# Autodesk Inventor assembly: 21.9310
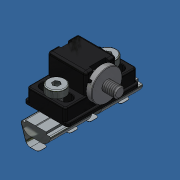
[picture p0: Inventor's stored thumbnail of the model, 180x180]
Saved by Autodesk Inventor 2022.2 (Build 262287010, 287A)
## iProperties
Created: 2022-08
Part Number: 21.9310
Document SubType Name: Assembly
Designer: amoles
Description: MAGNETIC CATCH 30
Stock Number: 21.9310 MAGNETIC CATCH 30
Author: amoles
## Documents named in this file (5)
- L:\INVENTOR LIBRARIES\PARTS LIBRARY\30 SERIES\21.9310 MAGNETIC CATCH 30.iam
- L:\INVENTOR LIBRARIES\PARTS LIBRARY\30 SERIES\SUBCOMPONENTS\21.9310_1 MAGNETIC CATCH 30.iam
- L:\INVENTOR LIBRARIES\PARTS LIBRARY\FASTENING ELEMENTS\SCREWS CAP\21.1229 M4x12.ipt
- 21.1229 SHCS M4X12 DIN 7984.ipt
- L:\INVENTOR LIBRARIES\PARTS LIBRARY\30 SERIES\21.2340_2 M4 SQUARE NUT 30 POS FXG.ipt
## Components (5 placed, 3 different names)
1. 21.9310_1 MAGNETIC CATCH 30:1 [sub-assembly] — Mate:1, Flush:1, Mate:2, Mate:3, Mate:4, Mate:5, Mate:6, Mate:7, Mate:8, Mate:11, Mate:12, Angle:1, Angle:2
2. 21.1229 SHCS M4X12 DIN 7984:1 — Mate:5, Mate:6, Mate:8, Mate:9
3. 21.1229 SHCS M4X12 DIN 7984:2 — Mate:3, Mate:4, Mate:7, Mate:10
4. 21.2340_2 M4 SQUARE NUT 30 POS FXG:1 — Mate:9, Mate:11, Angle:2
5. 21.2340_2 M4 SQUARE NUT 30 POS FXG:2 — Mate:10, Mate:12, Angle:1
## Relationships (15: Mate 12, Angle 2, Flush 1)
- Mate:1: 21.9310_1 MAGNETIC CATCH 30:1
- Flush:1: 21.9310_1 MAGNETIC CATCH 30:1
- Mate:2: 21.9310_1 MAGNETIC CATCH 30:1
- Mate:3: 21.9310_1 MAGNETIC CATCH 30:1 ↔ 21.1229 SHCS M4X12 DIN 7984:2
- Mate:4: 21.9310_1 MAGNETIC CATCH 30:1 ↔ 21.1229 SHCS M4X12 DIN 7984:2
- Mate:5: 21.9310_1 MAGNETIC CATCH 30:1 ↔ 21.1229 SHCS M4X12 DIN 7984:1
- Mate:6: 21.9310_1 MAGNETIC CATCH 30:1 ↔ 21.1229 SHCS M4X12 DIN 7984:1
- Mate:7: 21.9310_1 MAGNETIC CATCH 30:1 ↔ 21.1229 SHCS M4X12 DIN 7984:2
- Mate:8: 21.9310_1 MAGNETIC CATCH 30:1 ↔ 21.1229 SHCS M4X12 DIN 7984:1
- Mate:9: 21.1229 SHCS M4X12 DIN 7984:1 ↔ 21.2340_2 M4 SQUARE NUT 30 POS FXG:1
- Mate:10: 21.1229 SHCS M4X12 DIN 7984:2 ↔ 21.2340_2 M4 SQUARE NUT 30 POS FXG:2
- Mate:11: 21.9310_1 MAGNETIC CATCH 30:1 ↔ 21.2340_2 M4 SQUARE NUT 30 POS FXG:1
- Mate:12: 21.9310_1 MAGNETIC CATCH 30:1 ↔ 21.2340_2 M4 SQUARE NUT 30 POS FXG:2
- Angle:1: 21.9310_1 MAGNETIC CATCH 30:1 ↔ 21.2340_2 M4 SQUARE NUT 30 POS FXG:2
- Angle:2: 21.9310_1 MAGNETIC CATCH 30:1 ↔ 21.2340_2 M4 SQUARE NUT 30 POS FXG:1
